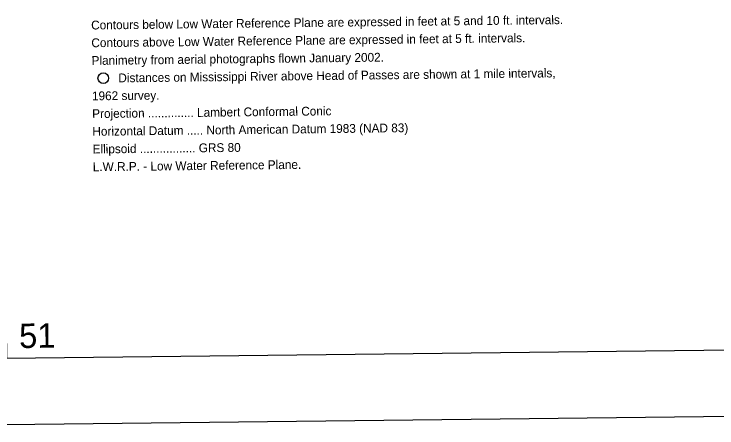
# Model space of a CAD drawing. Extents: x 3677843 to 3715951, y 511991 to 537744.
# Drawn here: x 3681519 to 3688133, y 512574 to 516468 of the extents above; entities that cross this region are included whole.
import ezdxf

# ---------------------------------------------------------------- set-up
doc = ezdxf.new("R2010")
doc.units = 0
for name, color, linetype in [('G-ANNO-NPLT', 7, 'Continuous'), ('V-ANNO-NOTE', 7, 'Continuous'), ('V-ANNO-SYMB', 7, 'Continuous'), ('V-ANNO-TEXT', 7, 'Continuous')]:
    doc.layers.add(name, color=color, linetype=linetype)

msp = doc.modelspace()

# ---------------------------------------------------------------- linework, layer by layer
at = {"layer": 'G-ANNO-NPLT'}
msp.add_lwpolyline([(3678703.9, 512574.2), (3715368.2, 512995.5), (3715090.5, 537160.6), (3678426.3, 536739.3)], close=True, dxfattribs=at)
at = {"layer": 'V-ANNO-NOTE'}
msp.add_circle((3682358.1, 515865.6), 50, dxfattribs=at)
at = {"layer": 'V-ANNO-SYMB'}
msp.add_lwpolyline([(3681446.7, 513230.8), (3714527.7, 513611), (3714264.4, 536526), (3681183.4, 536145.9), (3681446.7, 513230.8)], dxfattribs=at)

# ---------------------------------------------------------------- texts
at = {"layer": 'V-ANNO-NOTE'}
for s, rotation, p in [('Contours below Low Water Reference Plane are expressed in feet at 5 and 10 ft. intervals.', 0.65835, (3682244.6, 516322.9)), ('Contours above Low Water Reference Plane are expressed in feet at 5 ft. intervals.', 0.65835, (3682246.5, 516156.2)), ('Planimetry from aerial photographs flown January 2002.', 0.65835, (3682248.4, 515989.5)), ('Distances on Mississippi River above Head of Passes are shown at 1 mile intervals,', 0.65835, (3682500.5, 515825.7)), ('1962 survey.', 0.65835, (3682252.2, 515656.1)), ('Projection .............. Lambert Conformal Conic', 0.65832, (3682254.1, 515489.5)), ('Horizontal Datum ..... North American Datum 1983 (NAD 83)', 0.65832, (3682256, 515322.8)), ('Ellipsoid ................. GRS 80', 0.65832, (3682258, 515156.1)), ('L.W.R.P. - Low Water Reference Plane.', 0.65832, (3682259.9, 514989.4))]:
    msp.add_text(s, height=83, rotation=rotation, dxfattribs=at).set_placement(p)
at = {"layer": 'V-ANNO-TEXT'}
msp.add_text('51', height=230, rotation=0.65835, dxfattribs=at).set_placement((3681567.3, 513325.6))

doc.saveas('drawing.dxf')
